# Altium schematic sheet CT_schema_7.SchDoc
size 147 x 119 mm
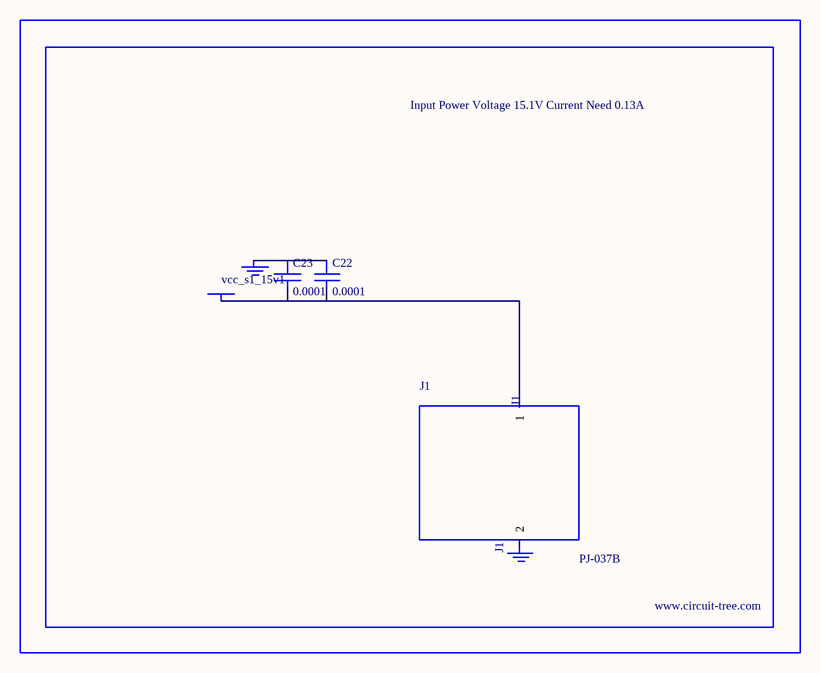
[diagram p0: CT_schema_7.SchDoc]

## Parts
BORDER6  (no value)
C22  0.0001  [EXV-9H]
C23  0.0001  [EXV-9H]
GND_INSTANCE_6_0  (no value)
GND_INSTANCE_6_1  (no value)
J1  PJ-037B  [PJ-037B_PACKAGE]
POWER_INSTANCE_6_0  vcc_s1_15v1

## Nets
NetC22_1: C22.1 C23.1 GND_INSTANCE_6_0.0(GND)
NetC22_2: C22.2 C23.2 J1.1 POWER_INSTANCE_6_0.0(PWR)

Not connected (* = marked no-connect by the designer): GND_INSTANCE_6_1 0(GND); J1 2

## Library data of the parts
BORDER6 = BORDER_PAGE6
C22 C23 = EDK107M035A9HAA
GND_INSTANCE_6_0 GND_INSTANCE_6_1 = GND
POWER_INSTANCE_6_0 = PWR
